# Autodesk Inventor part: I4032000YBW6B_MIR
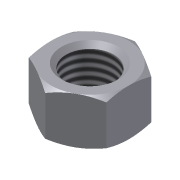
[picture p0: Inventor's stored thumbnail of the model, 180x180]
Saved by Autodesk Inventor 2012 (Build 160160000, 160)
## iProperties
Company: CAD-Verlag
Shininess: 64.0
Length Units: 11269
Angle Units: 11279
Time Units: 11290
Mass Units: 11283
Length Display Precision: 3
Angle Display Precision: 2
Compacted: True
Part Number: I4032000YBW6B_MIR
Document SubType Name: Modeling
Created: 2004-09
Material: Steel, Mild
Designer: Greiling
Manufacturer: Standard
Standards Organization: Custom
Density: 1 g/cm^3
Density: 0.0
Volumn: 0.0
Area: 0.0
PropertySet Name: Model Information
Control State: 0
Master: False
Checked Out: False
d64: 0,000 mm
Author: Jürgen Kronas
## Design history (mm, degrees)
node "Mutter DIN EN 24 032 M12" dims "d0" = 10, "d64" = 0
  node "WorkPlane8"
  node "WorkPlane10"
  node "MSC_PT1"
  node "MSC_PT2"
  node "MSC_PF1"
  node "MSC_A1"
  node "WorkPoint1"
  node "WorkPoint2"
node "Volumenkörper1"
node "Volumenkörpern"
node "Oberflächenkörpern"
tag "Bezeichnung2"
feature "Volumenkörper1::Mutter DIN EN 24 032 M12" dims "d0" = 10, "d64" = 0
